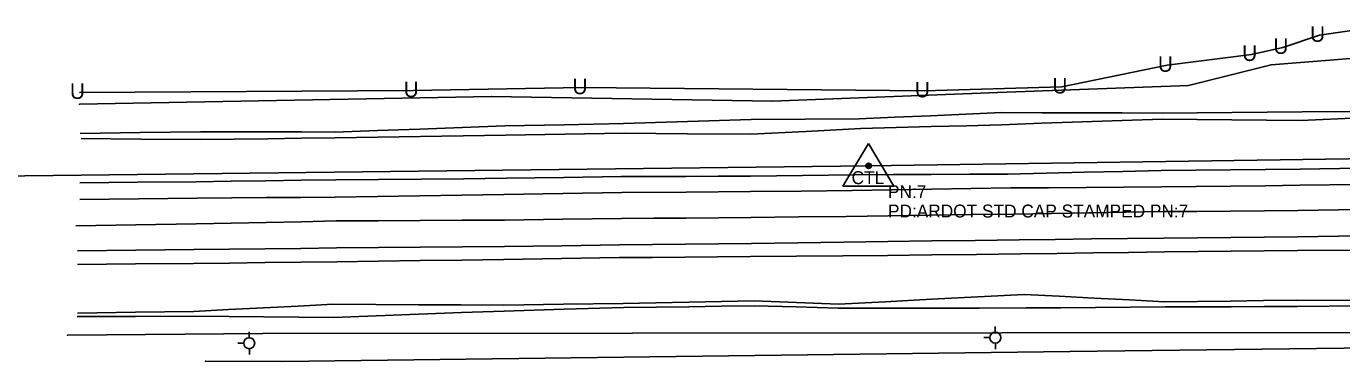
# Model space of a CAD drawing. Extents: x 1800653 to 1804042, y 522635 to 523313.
# Drawn here: x 1801222 to 1801731, y 522917 to 523047 of the extents above; entities that cross this region are included whole.
import ezdxf

# ---------------------------------------------------------------- set-up
doc = ezdxf.new("R2010")
doc.units = 0
for name, color, linetype in [('Default', 7, 'Continuous'), ('S_BASELINE', 7, 'Continuous'), ('S_DITCHLINE', 7, 'Continuous'), ('S_EDGE_PAVEMENT', 7, 'Continuous'), ('S_FIBER_OPTIC_CABLE', 7, 'Continuous'), ('S_GAS_UTILITIES', 7, 'Continuous'), ('S_PAVEMENT_CROWN', 7, 'Continuous'), ('S_PRIMARY_CTL', 7, 'Continuous'), ('S_PRIMARY_CTL_ANNOT', 7, 'Continuous'), ('S_SHOULDER', 7, 'Continuous'), ('S_UNDERGROUND_CABLE', 7, 'Continuous'), ('S_UTILITY_POLE', 7, 'Continuous'), ('S_UTL_PT_SYM', 7, 'Continuous'), ('S_WATER_UTILITIES', 7, 'Continuous')]:
    doc.layers.add(name, color=color, linetype=linetype)

msp = doc.modelspace()

# ---------------------------------------------------------------- linework, layer by layer
at = {"layer": 'S_BASELINE'}
for p, q in [((1801547.65, 522992.81), (1802220.63, 523002.66)), ((1800662.56, 522982.34), (1801547.65, 522992.81))]:
    msp.add_line(p, q, dxfattribs=at)
at = {"layer": 'S_DITCHLINE'}
for points in [[(1801242.32, 523005.38), (1801265.62, 523005.7), (1801288.91, 523006.03), (1801301.96, 523005.99), (1801315, 523005.96), (1801328.05, 523005.92), (1801341.09, 523005.89), (1801357.51, 523006.48), (1801373.92, 523007.07), (1801390.34, 523007.66), (1801406.75, 523008.25), (1801429.76, 523008.74), (1801452.78, 523009.23), (1801477.51, 523009.97), (1801502.24, 523010.7), (1801523.14, 523010.87), (1801544.05, 523011.04), (1801557.81, 523011.63), (1801571.57, 523012.23), (1801585.33, 523012.83), (1801599.09, 523013.43), (1801614.66, 523013.39), (1801630.23, 523013.35), (1801645.79, 523013.31), (1801661.36, 523013.26), (1801674.9, 523013.37), (1801688.44, 523013.47), (1801701.98, 523013.57), (1801715.52, 523013.67), (1801737.96, 523013.82)], [(1801242.7, 523003.35), (1801265.8, 523003.15), (1801288.89, 523002.96), (1801301.96, 523003.14), (1801315.02, 523003.32), (1801328.08, 523003.49), (1801341.14, 523003.67), (1801357.65, 523003.92), (1801374.15, 523004.18), (1801390.66, 523004.43), (1801407.16, 523004.68), (1801430.09, 523005.07), (1801453.02, 523005.46), (1801477.56, 523005.24), (1801502.11, 523005.02), (1801523.4, 523006.14), (1801544.68, 523007.26), (1801558.3, 523007.62), (1801571.91, 523007.99), (1801585.53, 523008.36), (1801599.14, 523008.72), (1801614.71, 523009.27), (1801630.28, 523009.82), (1801645.85, 523010.37), (1801661.42, 523010.92), (1801674.83, 523010.78), (1801688.24, 523010.63), (1801701.65, 523010.49), (1801715.06, 523010.34), (1801737.8, 523011.35)], [(1801241.3, 522935.83), (1801263.86, 522936.15), (1801286.41, 522936.47), (1801299.87, 522937.15), (1801313.33, 522937.83), (1801326.8, 522938.51), (1801340.26, 522939.19), (1801356.79, 522939.11), (1801373.32, 522939.03), (1801389.86, 522938.95), (1801406.39, 522938.87), (1801429.51, 522939.21), (1801452.62, 522939.56), (1801465.31, 522939.8), (1801477.99, 522940.05), (1801490.68, 522940.29), (1801503.36, 522940.54), (1801519.71, 522939.9), (1801536.05, 522939.27), (1801554.01, 522940.2), (1801571.96, 522941.14), (1801589.91, 522942.07), (1801607.86, 522943.01), (1801621.46, 522942.3), (1801635.05, 522941.58), (1801648.65, 522940.87), (1801662.25, 522940.16), (1801675, 522940.32), (1801687.75, 522940.48), (1801700.51, 522940.64), (1801713.26, 522940.8), (1801737.87, 522940.67)], [(1801241.2, 522934.52), (1801263.83, 522934.54), (1801286.47, 522934.56), (1801299.98, 522934.45), (1801313.5, 522934.35), (1801327.01, 522934.24), (1801340.53, 522934.13), (1801357.03, 522934.74), (1801373.53, 522935.36), (1801390.03, 522935.97), (1801406.54, 522936.58), (1801429.73, 522937.28), (1801452.93, 522937.99), (1801465.52, 522938.13), (1801478.1, 522938.28), (1801490.69, 522938.42), (1801503.28, 522938.57), (1801519.58, 522938.17), (1801535.88, 522937.77), (1801554.07, 522937.77), (1801572.26, 522937.77), (1801590.45, 522937.77), (1801608.64, 522937.78), (1801622.09, 522937.89), (1801635.55, 522938), (1801649, 522938.12), (1801662.45, 522938.23), (1801675.24, 522938.25), (1801688.04, 522938.28), (1801700.83, 522938.3), (1801713.63, 522938.32), (1801738.18, 522938.62)]]:
    msp.add_lwpolyline(points, dxfattribs=at)
at = {"layer": 'S_EDGE_PAVEMENT'}
for points in [[(1801242.18, 522979.84), (1801264.94, 522980.04), (1801287.7, 522980.23), (1801301.06, 522980.36), (1801314.42, 522980.49), (1801327.78, 522980.61), (1801341.14, 522980.74), (1801357.47, 522980.99), (1801373.8, 522981.24), (1801390.12, 522981.49), (1801406.45, 522981.75), (1801429.25, 522982.13), (1801452.05, 522982.51), (1801476.99, 522982.67), (1801501.92, 522982.84), (1801521.6, 522983.06), (1801541.28, 522983.28), (1801556.65, 522983.52), (1801572.01, 522983.76), (1801587.37, 522984), (1801602.73, 522984.23), (1801617.33, 522984.34), (1801631.93, 522984.44), (1801646.53, 522984.55), (1801661.13, 522984.66), (1801674.51, 522984.81), (1801687.88, 522984.97), (1801701.26, 522985.12), (1801714.64, 522985.27), (1801737.72, 522985.6)], [(1801241.34, 522959.86), (1801263.89, 522960.11), (1801286.44, 522960.37), (1801300.22, 522960.53), (1801314.01, 522960.69), (1801327.79, 522960.84), (1801341.57, 522961), (1801357.84, 522961.14), (1801374.11, 522961.27), (1801390.38, 522961.41), (1801406.65, 522961.54), (1801428.9, 522961.89), (1801451.15, 522962.23), (1801463.94, 522962.34), (1801476.74, 522962.45), (1801489.53, 522962.56), (1801502.33, 522962.68), (1801520.22, 522962.98), (1801538.11, 522963.29), (1801555.05, 522963.51), (1801572, 522963.73), (1801588.95, 522963.95), (1801605.9, 522964.18), (1801619.91, 522964.34), (1801633.93, 522964.5), (1801647.94, 522964.67), (1801661.95, 522964.83), (1801674.9, 522964.97), (1801687.86, 522965.1), (1801700.81, 522965.23), (1801713.77, 522965.37), (1801737.52, 522965.71)]]:
    msp.add_lwpolyline(points, dxfattribs=at)
at = {"layer": 'S_FIBER_OPTIC_CABLE'}
for p, q in [((1801761.16, 523036.49), (1801703.49, 523031.9)), ((1801703.49, 523031.9), (1801671.48, 523023.97)), ((1801671.48, 523023.97), (1801597.65, 523021.22)), ((1801401.66, 523019.62), (1801242.16, 523016.67)), ((1801510.3, 523017.85), (1801401.66, 523019.62)), ((1801597.65, 523021.22), (1801510.3, 523017.85))]:
    msp.add_line(p, q, dxfattribs=at)
at = {"layer": 'S_GAS_UTILITIES'}
for p, q in [((1801237.51, 522927.22), (1801313.07, 522927.87)), ((1801313.07, 522927.87), (1801836.17, 522928.43))]:
    msp.add_line(p, q, dxfattribs=at)
at = {"layer": 'S_PAVEMENT_CROWN'}
msp.add_lwpolyline([(1801240.63, 522969.52), (1801263.98, 522969.91), (1801287.33, 522970.3), (1801300.86, 522970.6), (1801314.39, 522970.89), (1801327.92, 522971.19), (1801341.45, 522971.48), (1801357.74, 522971.57), (1801374.03, 522971.65), (1801390.32, 522971.74), (1801406.61, 522971.83), (1801429.3, 522972.1), (1801451.99, 522972.36), (1801464.51, 522972.49), (1801477.03, 522972.61), (1801489.55, 522972.74), (1801502.07, 522972.86), (1801520.54, 522973.05), (1801539, 522973.24), (1801555.27, 522973.46), (1801571.54, 522973.69), (1801587.81, 522973.91), (1801604.07, 522974.14), (1801618.48, 522974.37), (1801632.89, 522974.6), (1801647.29, 522974.84), (1801661.7, 522975.07), (1801674.77, 522975.19), (1801687.83, 522975.31), (1801700.9, 522975.42), (1801713.96, 522975.54), (1801737.32, 522975.87)], dxfattribs=at)
at = {"layer": 'S_PRIMARY_CTL'}
for p, q in [((1801547.65, 523001.51), (1801537.61, 522985)), ((1801547.65, 523001.51), (1801557.47, 522985)), ((1801537.61, 522985), (1801557.47, 522985))]:
    msp.add_line(p, q, dxfattribs=at)
for radius in [1.04, 0.609, 0.344]:
    msp.add_circle((1801547.65, 522992.81), radius, dxfattribs=at)
at = {"layer": 'S_SHOULDER'}
for points in [[(1801242.25, 522986.26), (1801264.76, 522986.44), (1801287.27, 522986.62), (1801300.79, 522986.82), (1801314.32, 522987.02), (1801327.85, 522987.22), (1801341.37, 522987.42), (1801357.88, 522987.56), (1801374.4, 522987.7), (1801390.91, 522987.84), (1801407.43, 522987.99), (1801429.63, 522988.31), (1801451.84, 522988.64), (1801464.34, 522988.69), (1801476.85, 522988.74), (1801489.35, 522988.8), (1801501.86, 522988.85), (1801522.07, 522989.12), (1801542.27, 522989.39), (1801557.1, 522989.44), (1801571.93, 522989.5), (1801586.77, 522989.56), (1801601.6, 522989.61), (1801616.42, 522989.96), (1801631.24, 522990.3), (1801646.06, 522990.64), (1801660.88, 522990.98), (1801674.35, 522991.11), (1801687.81, 522991.25), (1801701.28, 522991.38), (1801714.74, 522991.51), (1801737.74, 522991.89)], [(1801241.37, 522954.62), (1801263.82, 522954.82), (1801286.27, 522955.03), (1801300.14, 522955.18), (1801314, 522955.34), (1801327.87, 522955.49), (1801341.74, 522955.65), (1801357.89, 522955.88), (1801374.04, 522956.12), (1801390.2, 522956.35), (1801406.35, 522956.59), (1801428.72, 522956.94), (1801451.08, 522957.28), (1801463.79, 522957.37), (1801476.49, 522957.47), (1801489.2, 522957.56), (1801501.9, 522957.66), (1801519.79, 522957.8), (1801537.68, 522957.95), (1801554.91, 522958.14), (1801572.14, 522958.32), (1801589.37, 522958.51), (1801606.61, 522958.7), (1801620.51, 522958.89), (1801634.42, 522959.08), (1801648.33, 522959.27), (1801662.23, 522959.46), (1801675.11, 522959.61), (1801687.98, 522959.76), (1801700.86, 522959.92), (1801713.73, 522960.07), (1801737.7, 522960.19)]]:
    msp.add_lwpolyline(points, dxfattribs=at)
at = {"layer": 'S_UNDERGROUND_CABLE'}
for p, q in [((1801722.21, 523043.37), (1801740.9, 523046.07)), ((1801708.02, 523038.68), (1801722.21, 523043.37)), ((1801663.31, 523031.76), (1801695.94, 523035.96)), ((1801695.94, 523035.96), (1801708.02, 523038.68)), ((1801622.47, 523023.38), (1801663.31, 523031.76)), ((1801242.05, 523021.25), (1801371.28, 523021.92)), ((1801371.28, 523021.92), (1801436.64, 523023.08)), ((1801436.64, 523023.08), (1801569.2, 523021.87)), ((1801569.2, 523021.87), (1801622.47, 523023.38))]:
    msp.add_line(p, q, dxfattribs=at)
at = {"layer": 'S_UTILITY_POLE'}
for p, q in [((1801307.81, 522926.26), (1801307.81, 522928.5)), ((1801596.7, 522928.42), (1801596.7, 522930.67)), ((1801305.72, 522924.12), (1801303.39, 522924.12)), ((1801594.6, 522926.29), (1801592.28, 522926.29)), ((1801596.77, 522921.88), (1801596.77, 522924.2)), ((1801307.89, 522919.71), (1801307.89, 522922.03))]:
    msp.add_line(p, q, dxfattribs=at)
for centre in [(1801596.7, 522926.31), (1801307.81, 522924.15)]:
    msp.add_circle(centre, 2.13, dxfattribs=at)
at = {"layer": 'S_UTL_PT_SYM'}
for points in [[(1801703.49, 523031.9), (1801703.49, 523031.95), (1801703.49, 523031.9), (1801703.44, 523031.9), (1801703.49, 523031.9), (1801703.49, 523031.85), (1801703.49, 523031.9), (1801703.54, 523031.9)], [(1801671.48, 523023.97), (1801671.48, 523024.02), (1801671.48, 523023.97), (1801671.43, 523023.97), (1801671.48, 523023.97), (1801671.48, 523023.92), (1801671.48, 523023.97), (1801671.53, 523023.97)], [(1801401.66, 523019.62), (1801401.66, 523019.67), (1801401.66, 523019.62), (1801401.61, 523019.62), (1801401.66, 523019.62), (1801401.66, 523019.57), (1801401.66, 523019.62), (1801401.71, 523019.62)], [(1801597.65, 523021.22), (1801597.65, 523021.27), (1801597.65, 523021.22), (1801597.6, 523021.22), (1801597.65, 523021.22), (1801597.65, 523021.17), (1801597.65, 523021.22), (1801597.7, 523021.22)], [(1801242.16, 523016.67), (1801242.16, 523016.72), (1801242.16, 523016.67), (1801242.11, 523016.67), (1801242.16, 523016.67), (1801242.16, 523016.62), (1801242.16, 523016.67), (1801242.21, 523016.67)], [(1801510.3, 523017.85), (1801510.3, 523017.9), (1801510.3, 523017.85), (1801510.25, 523017.85), (1801510.3, 523017.85), (1801510.3, 523017.8), (1801510.3, 523017.85), (1801510.35, 523017.85)], [(1801237.51, 522927.22), (1801237.51, 522927.27), (1801237.51, 522927.22), (1801237.46, 522927.22), (1801237.51, 522927.22), (1801237.51, 522927.17), (1801237.51, 522927.22), (1801237.56, 522927.22)], [(1801313.07, 522927.87), (1801313.07, 522927.92), (1801313.07, 522927.87), (1801313.02, 522927.87), (1801313.07, 522927.87), (1801313.07, 522927.82), (1801313.07, 522927.87), (1801313.12, 522927.87)], [(1801290.91, 522917.15), (1801290.91, 522917.2), (1801290.91, 522917.15), (1801290.86, 522917.15), (1801290.91, 522917.15), (1801290.91, 522917.1), (1801290.91, 522917.15), (1801290.96, 522917.15)], [(1801320.68, 522917.03), (1801320.68, 522917.08), (1801320.68, 522917.03), (1801320.63, 522917.03), (1801320.68, 522917.03), (1801320.68, 522916.98), (1801320.68, 522917.03), (1801320.73, 522917.03)], [(1801625.6, 522920.92), (1801625.6, 522920.97), (1801625.6, 522920.92), (1801625.55, 522920.92), (1801625.6, 522920.92), (1801625.6, 522920.87), (1801625.6, 522920.92), (1801625.65, 522920.92)]]:
    msp.add_lwpolyline(points, dxfattribs=at)
at = {"layer": 'S_WATER_UTILITIES'}
for p, q in [((1801625.6, 522920.92), (1801876.84, 522923.94)), ((1801290.91, 522917.15), (1801320.68, 522917.03)), ((1801320.68, 522917.03), (1801625.6, 522920.92))]:
    msp.add_line(p, q, dxfattribs=at)

# ---------------------------------------------------------------- texts
at = {"layer": 'Default'}
for p in [(1801718.58, 523040.83), (1801692.31, 523033.41), (1801704.39, 523036.14), (1801659.68, 523029.22), (1801238.42, 523018.71), (1801367.65, 523019.37), (1801433.01, 523020.54), (1801565.57, 523019.32), (1801618.84, 523020.83)]:
    msp.add_text('U', height=6, dxfattribs=at).set_placement(p)
at = {"layer": 'S_PRIMARY_CTL'}
msp.add_text('CTL', height=5, dxfattribs=at).set_placement((1801541.06, 522985.73))
at = {"layer": 'S_PRIMARY_CTL_ANNOT'}
for s, p in [('PN:7', (1801555.15, 522980.31)), ('PD:ARDOT STD CAP STAMPED PN:7', (1801555.15, 522972.81))]:
    msp.add_text(s, height=5, dxfattribs=at).set_placement(p)

doc.saveas('drawing.dxf')
